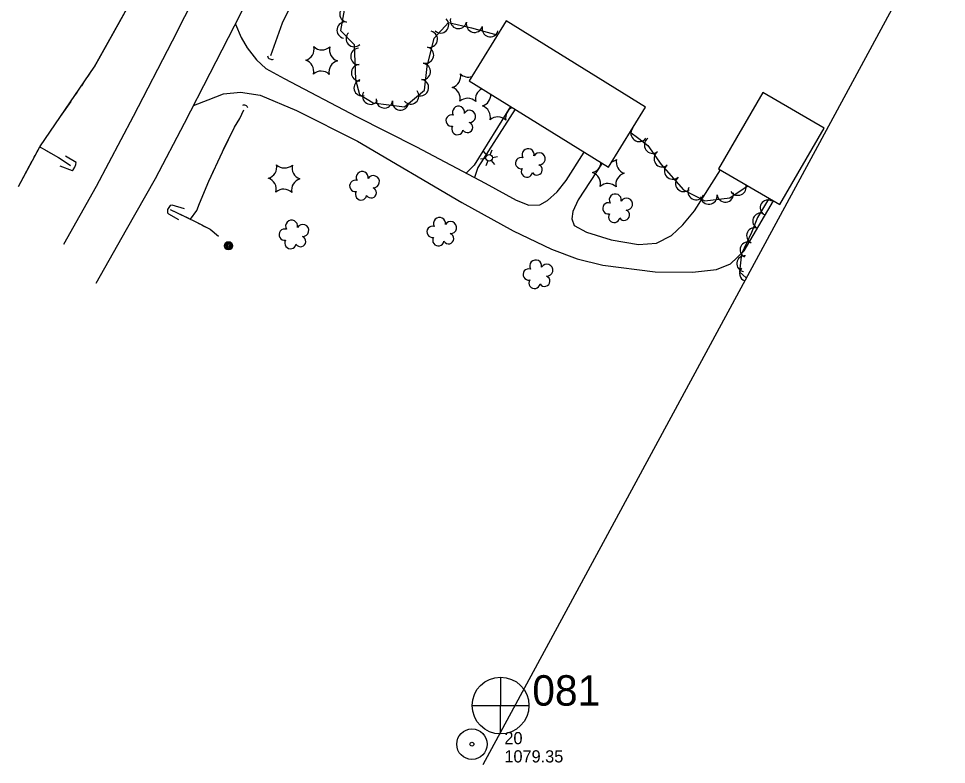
# Model space of a CAD drawing. Extents: x 296807 to 298965, y 28597 to 31038.
# Drawn here: x 297340.4 to 297797.6, y 29463.2 to 29830.6 of the extents above; entities that cross this region are included whole.
import ezdxf

# ---------------------------------------------------------------- set-up
doc = ezdxf.new("R2010")
doc.units = 0
for name, color, linetype in [('Level 11', 7, 'Continuous'), ('Level 12', 7, 'Continuous'), ('Level 14', 7, 'Continuous'), ('Level 15', 7, 'Continuous'), ('Level 17', 7, 'Continuous'), ('Level 18', 7, 'Continuous'), ('Level 19', 7, 'Continuous'), ('Level 4', 7, 'Continuous'), ('Level 6', 7, 'Continuous')]:
    doc.layers.add(name, color=color, linetype=linetype)

msp = doc.modelspace()

# ---------------------------------------------------------------- linework, layer by layer
at = {"layer": 'Level 11'}
for points in [[(297362.71, 29719.4), (297378.87, 29748.03), (297396.96, 29782.48), (297416.26, 29819.6), (297434.51, 29855.75), (297450.27, 29887.63), (297468.09, 29924.35), (297486.75, 29963.38), (297501.02, 29995.76), (297517.81, 30035.11), (297535.6, 30078.66), (297553.22, 30122.68), (297567.66, 30161.55), (297583.08, 30203.9), (297595.9, 30241.58), (297607.58, 30278.48), (297621.4, 30323.33), (297635.16, 30371.8), (297647.12, 30416.96)], [(297378.59, 29700.24), (297393.58, 29726.65), (297407.83, 29751.86), (297422.11, 29779.13), (297434.82, 29803.7), (297449.75, 29832.81), (297465.06, 29863.61), (297481.42, 29897.68), (297500.11, 29936.74), (297515.73, 29970.53), (297530.3, 30003.09), (297546.5, 30041.89), (297558.97, 30072.8), (297573.69, 30110.86), (297588.38, 30149.4), (297602.59, 30189.2), (297614.71, 30224.55), (297627.47, 30263.56), (297638.09, 30296.89), (297648.67, 30332.34), (297660.56, 30374.97), (297669.04, 30406.87)]]:
    msp.add_lwpolyline(points, dxfattribs=at)
at = {"layer": 'Level 12'}
for points in [[(297562.42, 29799.91), (297631.07, 29757.48), (297649.33, 29787.02), (297580.68, 29829.45)], [(297715.51, 29739.05), (297737.32, 29776.55), (297707.05, 29794.15), (297685.25, 29756.64)]]:
    msp.add_lwpolyline(points, close=True, dxfattribs=at)
at = {"layer": 'Level 14'}
for p, q in [((297571.2, 29763.33), (297569.54, 29765.35)), ((297572.8, 29763.54), (297573.7, 29765.9)), ((297570.62, 29761.72), (297568.06, 29761.35)), ((297571.63, 29760.48), (297570.71, 29758.05)), ((297573.29, 29760.7), (297574.91, 29758.69)), ((297573.88, 29762.23), (297576.34, 29762.69))]:
    msp.add_line(p, q, dxfattribs=at)
for centre, radius in [((297572.24, 29762), 1.64), ((297443.86, 29718.69), 2.02), ((297443.85, 29718.69), 1.52), ((297443.89, 29718.69), 1.01), ((297443.88, 29718.69), 0.502)]:
    msp.add_circle(centre, radius, dxfattribs=at)
at = {"layer": 'Level 15'}
for points in [[(297360.73, 29758.14), (297366.84, 29755.75), (297367.22, 29756.08), (297368.11, 29757.35), (297368.65, 29758.67), (297368.74, 29759.67), (297363.56, 29762.87)], [(297422.21, 29736.92), (297416.11, 29738.76), (297415.16, 29738.46), (297414.39, 29737.59), (297413.78, 29736.52), (297413.7, 29734.99), (297414.19, 29734.42), (297419.27, 29731.56)]]:
    msp.add_lwpolyline(points, dxfattribs=at)
for centre, radius, start, end in [((297465.13, 29812.57), 2.09, 189.2248, 295.4643), ((297451.63, 29786.17), 1.84, 13.819, 120.0585)]:
    msp.add_arc(centre, radius, start, end, dxfattribs=at)
at = {"layer": 'Level 17'}
for points in [[(297447.23, 29827.89), (297450, 29821.24), (297453, 29816.13), (297457.59, 29810.25), (297462.3, 29806.07), (297471.28, 29801.12), (297506.96, 29782.33), (297536.46, 29767.39), (297570.34, 29749.55), (297585.64, 29741.2), (297591.78, 29738.63), (297597.26, 29738.87), (297600.95, 29740.94), (297605.84, 29745.26), (297610.28, 29750.79), (297619.12, 29764.87)], [(297426.6, 29787.81), (297433.89, 29790.66), (297441.3, 29793.49), (297449.72, 29794.37), (297459.46, 29792.93), (297477.28, 29785.39), (297507.32, 29770.21), (297558.81, 29740.03), (297584.11, 29726.08), (297603.04, 29716.98), (297615.67, 29712.25), (297628.24, 29709.18), (297654.06, 29705.92), (297672.48, 29705.62), (297684.25, 29707.08), (297691.2, 29709.85), (297697.89, 29716.22), (297712.41, 29740.85)], [(297582.84, 29787.29), (297564.87, 29758.47), (297560.93, 29754.5)], [(297585.07, 29785.91), (297566.74, 29757.32), (297565.01, 29752.35)], [(297627.88, 29759.45), (297616.19, 29741.28), (297613.58, 29735.62), (297612.96, 29732.03), (297614.08, 29728.71), (297620.24, 29725.41), (297632.42, 29721.65), (297645.93, 29719.37), (297654.73, 29719.9), (297662.16, 29723.8), (297667.73, 29729.08), (297673.53, 29735.91), (297686.22, 29756.08)]]:
    msp.add_lwpolyline(points, dxfattribs=at)
at = {"layer": 'Level 18'}
for points in [[(297502.86, 29845.93), (297499.09, 29824.81), (297505.7, 29817.76), (297506.41, 29800.53), (297508.35, 29793.2), (297515.16, 29789.14), (297530.48, 29787.13), (297540.44, 29795.39), (297541.73, 29806.96), (297545.11, 29820.97), (297552.32, 29828.67), (297563.63, 29826.01), (297576.05, 29822.56)], [(297641.63, 29774.79), (297646, 29771.6), (297650.41, 29768.04), (297657.01, 29758.75), (297668.1, 29746.26), (297678.47, 29740.82), (297690.8, 29742.38), (297699.4, 29748.11)], [(297709.9, 29741.72), (297704.48, 29732.55), (297701.52, 29725.26), (297696.67, 29714.79), (297695.59, 29705.9), (297698.95, 29702.82)]]:
    msp.add_lwpolyline(points, dxfattribs=at)
for centre, radius, start, end in [((297502.66, 29832.82), 4.01, 79.8928, 259.8774), ((297501.25, 29824.92), 4.01, 79.8928, 259.8774), ((297548.34, 29827.49), 4.01, 226.8667, 46.8513), ((297557.13, 29829.7), 4.01, 166.7801, 346.7648), ((297565.02, 29827.81), 4.01, 164.489, 344.4737), ((297542.82, 29820.44), 4.01, 256.4498, 76.4344), ((297572.75, 29825.66), 4.01, 164.489, 344.4737), ((297505.78, 29820.74), 4.01, 133.1287, 313.1134), ((297480.33, 29815.62), 5.72, 285.8915, 11.6564), ((297489.92, 29820.89), 5.72, 225.8915, 311.6565), ((297499.28, 29815.22), 5.72, 165.8915, 251.6565), ((297508.04, 29811.95), 4.01, 92.364, 272.3487), ((297540.94, 29812.64), 4.01, 256.4498, 76.4344), ((297480.1, 29804.69), 5.72, 345.8915, 71.6564), ((297499.04, 29804.28), 5.72, 105.8915, 191.6565), ((297508.37, 29803.93), 4.01, 92.364, 272.3487), ((297539.35, 29804.52), 4.01, 263.6501, 83.6348), ((297489.45, 29799.01), 5.72, 45.8915, 131.6564), ((297552.53, 29802.22), 5.72, 285.8915, 11.6564), ((297562.12, 29807.49), 5.72, 225.8915, 286.1159), ((297509.65, 29796.52), 4.01, 104.8797, 284.8644), ((297538.46, 29796.55), 4.01, 263.6501, 83.6348), ((297552.3, 29791.29), 5.72, 345.8915, 71.6564), ((297513.85, 29792.36), 4.01, 149.1791, 329.1638), ((297533.64, 29792.48), 4.01, 219.6954, 39.68), ((297571.25, 29790.88), 5.72, 116.1932, 191.6565), ((297567.37, 29793.06), 5.72, 285.8915, 2.5417), ((297520.64, 29790.54), 4.01, 172.524, 352.5087), ((297528.59, 29789.49), 4.01, 172.524, 352.5087), ((297557.16, 29784.48), 2.97, 349.1039, 210.3378), ((297561.65, 29785.61), 5.72, 45.8915, 131.6564), ((297567.14, 29782.12), 5.72, 345.8915, 71.6564), ((297553.74, 29780.34), 2.78, 72.0748, 279.8478), ((297562.65, 29782.44), 2.97, 266.7547, 149.728), ((297586.09, 29781.72), 5.72, 116.2808, 191.6565), ((297561.56, 29777.02), 2.61, 211.4599, 69.3925), ((297576.5, 29776.45), 5.72, 45.8915, 131.6564), ((297556.6, 29776.16), 2.78, 148.7518, 349.7628), ((297646.2, 29774.1), 4.09, 143.8097, 323.7943), ((297652.85, 29768.3), 4.09, 125.4179, 305.4026), ((297591.45, 29763.56), 2.97, 349.1039, 210.3378), ((297596.94, 29761.52), 2.97, 266.7547, 149.728), ((297657.59, 29761.63), 4.09, 125.4179, 305.4026), ((297588.03, 29759.41), 2.78, 72.0748, 279.8478), ((297631.27, 29765.52), 5.72, 283.4544, 311.6565), ((297640.62, 29759.85), 5.72, 165.8915, 251.6565), ((297461.9, 29757.48), 5.72, 285.8915, 11.6564), ((297471.49, 29762.74), 5.72, 225.8915, 311.6565), ((297480.84, 29757.07), 5.72, 165.8915, 251.6565), ((297509.73, 29752.31), 2.97, 349.1039, 210.3378), ((297590.88, 29755.24), 2.78, 148.7518, 349.7628), ((297595.85, 29756.1), 2.61, 211.4599, 69.3925), ((297621.68, 29760.25), 5.72, 285.8915, 355.0797), ((297662.71, 29755.56), 4.09, 131.5945, 311.5792), ((297461.66, 29746.54), 5.72, 345.8915, 71.6564), ((297480.61, 29746.13), 5.72, 105.8915, 191.6565), ((297506.31, 29748.16), 2.78, 72.0748, 279.8478), ((297515.22, 29750.27), 2.97, 266.7547, 149.728), ((297621.44, 29749.31), 5.72, 345.8915, 71.6564), ((297640.39, 29748.91), 5.72, 105.8915, 191.6565), ((297668.14, 29749.44), 4.09, 131.5945, 311.5792), ((297471.02, 29740.87), 5.72, 45.8915, 131.6564), ((297514.13, 29744.85), 2.61, 211.4599, 69.3925), ((297630.8, 29743.64), 5.72, 45.8915, 131.6564), ((297674.26, 29745.45), 4.09, 152.3179, 332.3026), ((297694.81, 29747.62), 4.09, 213.7177, 16.7953), ((297509.17, 29743.98), 2.78, 148.7518, 349.7628), ((297634.43, 29741.25), 2.97, 349.1039, 210.3378), ((297639.92, 29739.21), 2.97, 266.7547, 149.728), ((297680.49, 29743.24), 4.09, 187.1967, 7.1814), ((297688.61, 29744.26), 4.09, 187.1967, 7.1814), ((297631.01, 29737.11), 2.78, 72.0748, 279.8478), ((297709.67, 29737.36), 3.86, 59.4526, 239.4373), ((297547.8, 29729.7), 2.97, 349.1039, 210.3378), ((297633.87, 29732.93), 2.78, 148.7518, 349.7628), ((297638.83, 29733.79), 2.61, 211.4599, 69.3925), ((297706, 29730.91), 3.86, 67.8383, 247.823), ((297474.92, 29728.3), 2.97, 349.1039, 210.3378), ((297480.41, 29726.26), 2.97, 266.7547, 149.728), ((297544.38, 29725.56), 2.78, 72.0748, 279.8478), ((297553.28, 29727.66), 2.97, 266.7547, 149.728), ((297471.5, 29724.15), 2.78, 72.0748, 279.8478), ((297479.32, 29720.84), 2.61, 211.4599, 69.3925), ((297552.2, 29722.25), 2.61, 211.4599, 69.3925), ((297703.01, 29723.69), 3.86, 65.1785, 245.1631), ((297474.36, 29719.98), 2.78, 148.7518, 349.7628), ((297547.23, 29721.38), 2.78, 148.7518, 349.7628), ((297699.77, 29716.67), 3.86, 65.1785, 245.1631), ((297595.2, 29708.71), 2.97, 349.1039, 210.3378), ((297600.68, 29706.67), 2.97, 266.7547, 149.728), ((297698.11, 29709.87), 3.86, 83.1057, 263.0904), ((297591.77, 29704.56), 2.78, 72.0748, 279.8478), ((297699.53, 29705.04), 3.86, 137.5276, 249.6467), ((297594.63, 29700.39), 2.78, 148.7518, 349.7628), ((297599.59, 29701.25), 2.61, 211.4599, 69.3925)]:
    msp.add_arc(centre, radius, start, end, dxfattribs=at)
at = {"layer": 'Level 19'}
for points in [[(297350.88, 29767.35), (297361.11, 29782.29), (297377.72, 29806.62), (297394.58, 29836.84), (297411.42, 29861.38), (297418.63, 29881.04), (297431.92, 29909.51), (297446.53, 29932.57), (297457.72, 29955.4), (297471.91, 29983.11), (297488.14, 30008.97), (297495.82, 30025.29), (297507.25, 30051.69), (297520.23, 30080.88), (297528.99, 30105.94), (297540.87, 30136.71), (297551.03, 30163.61), (297562.22, 30191.77), (297572.48, 30221.96), (297577.55, 30238.36)], [(297464.74, 29812.46), (297470.43, 29828.48), (297480.81, 29849.89), (297490.47, 29869.08), (297501.21, 29887.56), (297512.11, 29911.88), (297524.86, 29939.09), (297532.62, 29968.59), (297541.65, 29991.46), (297551.52, 30015.16), (297561.11, 30035.94), (297569.46, 30059.8), (297581.59, 30089.97), (297591.72, 30119.42), (297601.17, 30147.44), (297611.21, 30183.78), (297623.7, 30218.33)], [(297391.09, 29830.58), (297394.58, 29836.84), (297405.91, 29853.35)], [(297464.74, 29812.46), (297470.43, 29828.48), (297476.83, 29841.68)], [(297377.83, 29806.82), (297391.09, 29830.58)], [(297374.68, 29802.17), (297375.74, 29803.72)], [(297371.51, 29797.53), (297372.57, 29799.07)], [(297368.34, 29792.88), (297369.4, 29794.43)], [(297350.88, 29767.35), (297361.11, 29782.29), (297366.23, 29789.79)], [(297425.19, 29731.73), (297428.2, 29736.01), (297429.6, 29739.52), (297434.17, 29750.58), (297440.87, 29765.01), (297446.75, 29777.07), (297449.34, 29781.32), (297451.39, 29785.63)], [(297441.45, 29766.2), (297446.75, 29777.07), (297449.34, 29781.32), (297451.39, 29785.63)], [(297340.39, 29747.87), (297347.23, 29760.72), (297350.88, 29767.35), (297359.99, 29762.13), (297363.35, 29760.03), (297365.98, 29758.31)], [(297349.55, 29764.93), (297350.03, 29765.8)], [(297351.08, 29767.24), (297351.94, 29766.74)], [(297353.66, 29765.76), (297359.99, 29762.13), (297363.35, 29760.03), (297365.98, 29758.31)], [(297340.39, 29747.87), (297347.16, 29760.58)], [(297348.12, 29762.32), (297348.6, 29763.19)], [(297439.52, 29762.11), (297440.16, 29763.48)], [(297435.72, 29753.9), (297436.35, 29755.27)], [(297437.62, 29758.01), (297438.25, 29759.37)], [(297425.19, 29731.73), (297428.2, 29736.01), (297429.6, 29739.52), (297434.17, 29750.58), (297434.45, 29751.17)], [(297415.15, 29736.5), (297427.34, 29730.71), (297434.72, 29726.81), (297438.93, 29723.46)], [(297415.15, 29736.5), (297424.06, 29732.26)], [(297425.29, 29731.68), (297425.91, 29731.39)], [(297427.13, 29730.8), (297427.34, 29730.71), (297427.74, 29730.49)], [(297428.95, 29729.86), (297429.55, 29729.54)], [(297430.75, 29728.9), (297434.72, 29726.81), (297438.93, 29723.46)]]:
    msp.add_lwpolyline(points, dxfattribs=at)
at = {"layer": 'Level 4'}
for p, q in [((297577.84, 29506.22), (297577.77, 29478.36)), ((297563.93, 29492.19), (297591.83, 29492.17))]:
    msp.add_line(p, q, dxfattribs=at)
msp.add_lwpolyline([(297569.31, 29463.18), (297788.03, 29867.51), (297944.29, 30413.21), (297962.48, 30592.06)], dxfattribs=at)
msp.add_circle((297577.89, 29492.2), 14, dxfattribs=at)
at = {"layer": 'Level 6'}
for radius in [7.5, 0.96]:
    msp.add_circle((297563.79, 29473.15), radius, dxfattribs=at)

# ---------------------------------------------------------------- texts
at = {"layer": 'Level 4'}
msp.add_text('081', height=15, dxfattribs=at).set_placement((297593.54, 29492.13))
at = {"layer": 'Level 6'}
for s, p in [('20', (297579.79, 29473.15)), ('1079.35', (297579.79, 29464.15))]:
    msp.add_text(s, height=6, dxfattribs=at).set_placement(p)

doc.saveas('drawing.dxf')
